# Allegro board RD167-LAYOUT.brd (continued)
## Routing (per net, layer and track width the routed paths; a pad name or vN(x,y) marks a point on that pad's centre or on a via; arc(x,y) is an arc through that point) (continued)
+12V_Q6: length 28.9
  TOP w0.2: TP27.1 216.6,208.9
  TOP w0.5: 220.18,220.5 219.31,220.5 ; 220.45,219.27 220.45,220.23 ; 218.78,220.5 v2(217.75,220.5)
  TOP w0.6: v2(211.44,211.26) v2(213,211.26)
  TOP w0.7: 219.31,220.5 218.78,220.5
  TOP w0.8: C105.1 220.45,219.27 ; 220.45,220.23 R80.1 220.18,220.5
  CONDUCTIVE5 w0.5: v2(211.44,211.26) v2(213,211.26) 215.25,213.51 215.25,218 v2(217.75,220.5)
  BOTTOM w0.6: IC14.13 209.75,212.37 209.91,212.2 210.4,212.2 ; R89.1 211.44,210.46 v2(211.44,211.26) ; R90.1 213.3,210.74 v2(213,211.26) v2(211.44,211.26) ; C108.1 v2(211.44,211.26) ; v2(211.44,211.26) 210.67,210.48 210.5,210.03
  BOTTOM w0.8: C109.1 210.5,210.03 ; 210.4,212.2 C108.1
+12V_Q7: length 28.9
  TOP w0.2: TP32.1 216.6,158.9
  TOP w0.5: 220.45,169.27 220.45,170.23 ; 220.18,170.5 219.31,170.5 ; 218.78,170.5 v2(217.75,170.5)
  TOP w0.6: v2(211.44,161.26) v2(213,161.26)
  TOP w0.7: 219.31,170.5 218.78,170.5
  TOP w0.8: C117.1 220.45,169.27 ; 220.18,170.5 R92.1 220.45,170.23
  CONDUCTIVE5 w0.5: v2(211.44,161.26) v2(213,161.26) 215.25,163.51 215.25,168 v2(217.75,170.5)
  BOTTOM w0.6: v2(211.44,161.26) 210.67,160.48 210.5,160.03 ; v2(211.44,161.26) C120.1 ; v2(211.44,161.26) 211.44,160.46 R101.1 ; v2(211.44,161.26) v2(213,161.26) 213.3,160.74 R102.1 ; IC16.13 209.75,162.37 209.91,162.2 210.4,162.2
  BOTTOM w0.8: 210.4,162.2 C120.1 ; C121.1 210.5,160.03
+12V_Q8: length 28.9
  TOP w0.2: TP37.1 216.6,120.9
  TOP w0.5: 220.45,131.27 220.45,132.23 ; 218.78,132.5 v2(217.75,132.5) ; 220.18,132.5 219.31,132.5
  TOP w0.6: v2(211.44,123.26) v2(213,123.26)
  TOP w0.7: 219.31,132.5 218.78,132.5
  TOP w0.8: 220.45,132.23 R104.1 220.18,132.5 ; C137.1 220.45,131.27
  CONDUCTIVE5 w0.5: v2(211.44,123.26) v2(213,123.26) 215.25,125.51 215.25,130 v2(217.75,132.5)
  BOTTOM w0.6: v2(211.44,123.26) 211.44,122.46 R113.1 ; v2(211.44,123.26) 210.67,122.48 210.5,122.03 ; v2(211.44,123.26) C140.1 ; v2(211.44,123.26) v2(213,123.26) 213.3,122.74 R114.1 ; IC18.13 209.75,124.36 209.91,124.2 210.4,124.2
  BOTTOM w0.8: 210.4,124.2 C140.1 ; C141.1 210.5,122.03
+20V_Q1: length 27.8
  TOP w0.2: TP2.1 103.4,118.1
  TOP w0.5: C19.1 104.25,108 104.75,107.5 v2(104.75,106.5) 103.55,106.5
  TOP w0.6: v2(108.56,115.74) v2(107,115.74)
  TOP w0.8: R21.1 103.55,106.5
  CONDUCTIVE5 w0.5: v2(104.75,106.5) 104.75,113.49 v2(107,115.74) v2(108.56,115.74)
  BOTTOM w0.6: 109.61,114.8 110.08,114.8 110.25,114.64 IC4.13 ; v2(108.56,115.74) 109.33,116.52 109.5,116.97 ; v2(108.56,115.74) C24.1 ; v2(108.56,115.74) 108.56,116.54 R30.1 ; v2(108.56,115.74) v2(107,115.74) 106.7,116.26 R31.1
  BOTTOM w0.8: C23.1 109.5,116.97 ; 109.61,114.8 C24.1
+20V_Q2: length 27.8
  TOP w0.2: TP7.1 103.4,156.1
  TOP w0.5: C39.1 104.25,146 104.75,145.5 v2(104.75,144.5) 103.55,144.5
  TOP w0.6: v2(108.56,153.74) v2(107,153.74)
  TOP w0.8: R32.1 103.55,144.5
  CONDUCTIVE5 w0.5: v2(104.75,144.5) 104.75,151.49 v2(107,153.74) v2(108.56,153.74)
  BOTTOM w0.6: 109.5,154.97 109.33,154.52 v2(108.56,153.74) ; v2(108.56,153.74) v2(107,153.74) 106.7,154.26 R43.1 ; v2(108.56,153.74) C44.1 ; v2(108.56,153.74) 108.56,154.54 R42.1 ; 109.61,152.8 110.08,152.8 110.25,152.63 IC6.13
  BOTTOM w0.8: 109.61,152.8 C44.1 ; C43.1 109.5,154.97
+20V_Q3: length 27.8
  TOP w0.2: TP12.1 103.4,206.1
  TOP w0.5: C51.1 104.25,196 104.75,195.5 v2(104.75,194.5) 103.55,194.5
  TOP w0.6: v2(108.56,203.74) v2(107,203.74)
  TOP w0.8: R45.1 103.55,194.5
  CONDUCTIVE5 w0.5: v2(104.75,194.5) 104.75,201.49 v2(107,203.74) v2(108.56,203.74)
  BOTTOM w0.6: v2(108.56,203.74) 108.56,204.54 R54.1 ; v2(108.56,203.74) v2(107,203.74) 106.7,204.26 R55.1 ; v2(108.56,203.74) C56.1 ; v2(108.56,203.74) 109.33,204.52 109.5,204.97 ; 109.61,202.8 110.08,202.8 110.25,202.63 IC8.13
  BOTTOM w0.8: 109.61,202.8 C56.1 ; C55.1 109.5,204.97
+20V_Q4: length 27.8
  TOP w0.2: TP17.1 103.4,244.1
  TOP w0.5: C71.1 104.25,234 104.75,233.5 v2(104.75,232.5) 103.55,232.5
  TOP w0.6: v2(108.56,241.74) v2(107,241.74)
  TOP w0.8: R57.1 103.55,232.5
  CONDUCTIVE5 w0.5: v2(104.75,232.5) 104.75,239.49 v2(107,241.74) v2(108.56,241.74)
  BOTTOM w0.6: IC10.13 110.25,240.63 110.08,240.8 109.61,240.8 ; v2(108.56,241.74) 109.33,242.52 109.5,242.97 ; v2(108.56,241.74) C76.1 ; v2(108.56,241.74) v2(107,241.74) 106.7,242.26 R67.1 ; v2(108.56,241.74) 108.56,242.54 R66.1
  BOTTOM w0.8: C75.1 109.5,242.97 ; 109.61,240.8 C76.1
+24V: length 59.9
  TOP w0.3: 145.27,262 147.25,262 148,262.75 v2(148,264.25)
  TOP w0.8: 167,267.35 v2(167,265.75) v2(167,264.25) ; 148,267.35 v2(148,265.75) v2(148,264.25) ; v2(171,264.25) v2(171,265.75) 171,267.35
  TOP w1: CN2.1 148,267.35 ; CN3.1 167,267.35 ; CN3.3 171,267.35
  TOP w1.7: TP43.1 145.27,262
  CONDUCTIVE2 w0.5: PS8.1 196.63,173.55 ; PS8.1 196.63,170.45 ; PS8.1 195.08,172 ; PS2.1 123.37,106.55 ; PS2.1 123.37,103.45 ; PS2.1 124.92,105 ; PS3.1 123.37,141.45 ; PS3.1 124.92,143 ; PS3.1 123.37,144.55 ; PS7.1 195.08,222 ; PS7.1 196.63,223.55 ; PS7.1 196.63,220.45 ; PS4.1 124.92,193 ; PS4.1 123.37,191.45 ; PS4.1 123.37,194.55 ; PS5.1 124.92,231 ; PS5.1 123.37,229.45 ; PS5.1 123.37,232.55 ; PS6.1 195.08,260 ; PS6.1 196.63,261.55 ; PS6.1 196.63,258.45 ; PS9.1 195.08,134 ; PS9.1 196.63,135.55 ; PS9.1 196.63,132.45
  BOTTOM w0.8: v2(148,264.25) v2(148,265.75) ; v2(171,264.25) v2(171,265.75) ; v2(167,264.25) v2(167,265.75)
  vias: v2(163.75,254) v2(163.75,252.5)
GND: length 1762.2
  TOP w0.2: 162.98,155.25 164.75,155.25 v1(165,155) ; 157.18,167.44 156.31,167.44 v1(156,167.75) ; v1(165,157) 164.25,156.25 162.98,156.25 ; v1(165,157) 164.25,157.75 163.75,157.75 163.25,157.25 162.91,157.25 ; v1(165,157) 165,157.75 164.5,158.25 162.98,158.25 ; 162.98,153.75 163.75,153.75 v1(164,154) 163.75,154.25 162.98,154.25 ; v1(155,155) 155.25,155.25 157.02,155.25 ; 157.02,164.75 156.25,164.75 v1(156,164.5) ; 162.98,162.25 163.5,162.25 v1(164,162.75) ; 157.02,162.25 156.25,162.25 v1(156,162.5) ; 157.02,157.25 156.5,157.25 v1(156,157.75) 156.5,158.25 157.02,158.25 ; v1(164,160.5) 163.75,160.25 162.98,160.25 ; v1(155,157) 155.75,156.25 157.02,156.25 ; v1(164,168) 163.44,167.44 162.7,167.44 ; 157.02,154.25 156.25,154.25 v1(156,154) 156.25,153.75 157.02,153.75 ; v1(156,160.5) 156.25,160.25 157.02,160.25
  TOP w0.25: CN4.11 162.98,155.25 ; CN4.16 157.02,156.25 ; CN4.23 162.98,158.25 ; CN4.50 157.02,164.75 ; CN4.24 157.02,158.25 ; CN4.32 157.02,160.25 ; CN4.6 157.02,153.75 ; CN4.31 162.98,160.25 ; CN4.12 157.02,155.25 ; CN4.15 162.98,156.25 ; CN4.39 162.98,162.25 ; CN4.7 162.98,154.25 ; CN4.40 157.02,162.25 ; CN4.20 157.02,157.25 ; CN4.19 162.91,157.25 ; CN4.8 157.02,154.25 ; CN4.5 162.98,153.75
  TOP w0.3: v1(178.75,39) 180,40.25 180,41.51 ; v1(141.25,71.25) 140,70 140,68.74 ; 146.16,52 v1(144.75,52) ; v1(145.5,60.75) 146.5,60.75 146.84,61.09 146.84,61.8 ; TP45.1 v1(148,20) ; v1(137,243.75) 138,243.75 138.75,243 138.75,212.25 136.25,209.75 136.25,206.5 v1(137,205.75) 138,205.75 138.75,205 138.75,160.25 136.25,157.75 136.25,156.5 v1(137,155.75) 137.75,155.75 138.75,154.75 138.75,122.25 136.25,119.75 136.25,118.5 v1(137,117.75) 138,117.75 140.25,120 140.25,205.75 v1(138,208) ; 161.25,80.2 161.25,80.65 162.05,81.45 162.05,82.06 ; 170,215 170,189.25 168.25,187.5 163.75,187.5 v1(162.25,186) ; v1(183,121.25) 182,121.25 181.25,122 181.25,153.5 183.75,156 183.75,158.5 v1(183,159.25) 182,159.25 181.25,160 181.25,204.75 183.75,207.25 183.75,208.5 v1(183,209.25) 182.25,209.25 181.25,210.25 181.25,242.75 183.75,245.25 183.75,246.5 v1(183,247.25) 181.5,247.25 ; 150,26.01 v1(150,24.5) ; v1(176.25,25.75) 176.7,26.2 177.83,26.2 ; 162.24,82.25 v1(163.5,82.25) ; 146.86,53.75 v1(144.75,53.75) ; IC1.11 v1(158,73.75) 159.5,75.25 160.26,75.25 ; IC24.11 v1(173,73.75) ; v1(182,157) 179.75,159.25 179.75,244 ; 178.19,26.2 179.25,26.2 179.5,25.95 180.88,25.95 ; 152.54,60.8 153.55,60.8 v1(154,61.25)
  TOP w0.4: 159,12.5 v1(159,14)
  TOP w0.45: C8.2 146.86,53.75
  TOP w0.5: 142.17,37.8 143.3,37.8 v1(143.75,38.25) ; 139.12,38.05 140.75,38.05 141,37.8 141.72,37.8 ; IC23.2 161.25,80.2
  TOP w0.6: CN4.59 162.7,167.44 ; CN4.60 157.18,167.44 ; IC19.4 146.84,61.8
  TOP w0.8: 160.43,237.6 161.91,237.6 v2(162.5,237.5) ; 141.72,37.8 C1.2 142.17,37.8 ; 180,41.51 C153.2 ; 162.24,82.25 C174.2 162.05,82.06 ; D3.A 146.16,52 ; 177.83,26.2 C146.2 178.19,26.2 ; 159.57,237.6 157.65,237.6 157.6,237.65 PS11.7 ; 160.26,75.25 C175.2 ; C10.2 140,68.74 ; LED1.K 150,26.01 ; C158.2 152.54,60.8
  TOP w1: CN1.2 159,12.5
  TOP w1.2: 159.57,237.6 C163.2 160.43,237.6
  TOP w1.5: 139.12,38.05 CT1.13 ; 180.88,25.95 CT2.13
  CONDUCTIVE3 w0.5: PS11.7 156.45,237.65 ; PS11.7 155,239.1 ; PS11.7 153.55,237.65 ; PS11.7 155,236.2 ; CT1.13 140.42,38.05 ; CT2.13 179.58,25.95
  CONDUCTIVE4 w0.5: CT2.13 179.58,25.95 ; CT1.13 140.42,38.05 ; 153.55,237.65 PS11.7 156.45,237.65 ; 139.08,54.75 PS1.2 139.08,51.75 ; 181.42,54.75 PS10.2 181.42,57.75
  CONDUCTIVE5 w0.2: v1(124.1,114.64) 124.1,115.5 ; v1(124.1,202.63) 124.1,203.5 ; v1(124.1,152.63) 124.1,153.5 ; v1(124.1,240.63) 124.1,241.6
  CONDUCTIVE5 w0.3: 179.75,27.35 179.75,27.33 CT2.13 179.75,24.57 179.75,24.55 ; 140.25,36.7 140.22,36.7 CT1.13 140.22,39.4 140.25,39.4
  CONDUCTIVE5 w0.5: 139.08,54.75 PS1.2 139.08,51.75 ; 181.42,57.75 PS10.2 181.42,54.7
  BOTTOM w0.2: 163.12,138.93 163.12,140.5 ; 163.12,140.5 162.47,140.5 ; 163.12,140.5 163.78,140.5 ; 163.78,140.5 v1(165.25,140.5) ; 163.78,140.5 163.78,138.93 ; 162.47,140.5 162,140.5 161.82,140.32 161.82,138.93 ; 162.47,140.5 162.47,138.93
  BOTTOM w0.25: 196.93,168.88 194.55,168.88 ; v1(165.75,178.25) 176.75,167.25 176.75,126.5 182,121.25 v1(183,121.25) ; 123.08,146.12 125.45,146.12 ; 196.93,130.88 194.55,130.88 ; v1(183,159.25) 182,159.25 178.25,163 178.25,167.75 v1(167.25,178.75) ; v1(162.5,130) 147.25,130 140.75,136.5 140.75,202.75 137.75,205.75 v1(137,205.75) ; v1(138,208) 140.75,210.75 140.75,238.5 138.25,241 128.7,241 v1(127.7,240) ; v1(192.3,251) 191.3,250 183.25,250 v1(181.5,248.25) 176.75,243.5 176.75,192.25 v1(165.75,181.25) ; v1(167.25,180.75) 178.25,191.75 178.25,212 ; v1(137,243.75) 137.75,243.75 142.25,239.25 142.25,139.25 149.75,131.75 157.5,131.75 158,131.25 v1(163.75,131.25) ; 146.25,127 146.75,127.5 v1(162.5,127.5) ; 146.25,127 137.75,135.5 137.75,152.25 137,153 128.7,153 v1(127.7,152) ; 146.25,127 v1(137,117.75) ; v1(163.75,126.25) 163.25,125.75 147.5,125.75 v1(138.5,116.75) 136.75,115 128.7,115 v1(127.7,114) ; v1(183,209.25) 179.75,206 179.75,191.25 v1(168.25,179.75) 179.75,168.25 179.75,164 181.75,162 191.3,162 v1(192.3,163) ; v1(192.3,125) 191.3,124 182.25,124 178.25,128 178.25,153.25 v1(182,157) ; 196.93,256.88 194.55,256.88 ; 196.93,218.88 194.55,218.88 ; v1(192.3,213) 191.3,212 178.25,212 ; 123.08,234.12 125.45,234.12 ; 178.25,212 178.25,242.5 v1(183,247.25) ; 123.08,108.12 125.45,108.12 ; 123.08,196.12 125.45,196.12 ; v1(163.75,128.75) 146.5,128.75 139.25,136 139.25,154.25 137.75,155.75 v1(137,155.75) 139.25,158 139.25,201.75 138,203 128.7,203 v1(127.7,202)
  BOTTOM w0.3: C166.2 163.25,189.75 162.75,190.25 v1(161.25,190.25) 161.25,188.99 ; 164.51,139 164.51,139.76 v1(165.25,140.5) ; C164.2 155.7,136.3 v1(155.25,136.75) 155.25,139 156,139.75 158,139.75 158.49,139.26 158.49,138.84 ; v1(124.1,240.63) 124.77,241.3 126.6,241.3 127.7,242.4 135.65,242.4 v1(137,243.75) ; 163.78,184.75 163.25,184.75 163.12,184.62 IC22.8 ; 163.78,184.75 IC22.9 ; 163.78,184.75 164.25,184.75 164.51,184.49 164.51,184 ; v1(183,209.25) 184.35,210.6 192.3,210.6 193.4,211.7 195.24,211.7 v1(195.9,212.37) ; 142.95,63.7 142.95,62.7 v1(142.5,62.25) ; v1(183,121.25) 184.35,122.6 192.3,122.6 193.4,123.7 195.24,123.7 v1(195.9,124.36) ; v1(164.75,181.5) 164.51,181.74 164.51,182.8 ; 177.05,45.19 177.05,46.31 ; v1(124.1,114.64) 124.77,115.3 126.6,115.3 127.7,116.4 135.65,116.4 v1(137,117.75) ; 169.74,73.75 v1(173,73.75) ; v1(195.9,162.37) 195.24,161.7 193.4,161.7 192.3,160.6 184.35,160.6 v1(183,159.25) ; 156.69,136.3 158.2,136.3 159.22,135.28 IC21.19 ; v1(177.5,48) 177.05,47.55 177.05,46.55 ; 154.74,73.75 v1(158,73.75) ; v1(178.75,39) 179.06,38.69 IC20.5 ; v1(137,155.75) 135.65,154.4 127.7,154.4 126.6,153.3 124.77,153.3 v1(124.1,152.63) ; C165.2 155.7,181.3 v1(155.25,181.75) 155.75,182.25 158.25,182.25 158.49,182.49 158.49,182.96 ; IC22.19 159.22,180.32 158.25,181.3 156.69,181.3 ; v1(137,205.75) 135.65,204.4 127.7,204.4 126.6,203.3 124.77,203.3 v1(124.1,202.63) ; v1(195.9,250.37) 195.24,249.7 193.4,249.7 192.3,248.6 184.35,248.6 v1(183,247.25) ; 142.95,65.06 142.95,63.94 ; v1(141.25,71.25) 140.94,71.56 IC2.5 ; 167.75,129.25 167.75,135.75
  BOTTOM w0.35: IC21.6 161.82,138.93 ; IC21.7 162.47,138.93 ; IC21.9 163.78,138.93 ; IC21.8 163.12,138.93
  BOTTOM w0.5: v1(124.1,240.63) 122.48,240.63 ; v1(195.9,212.37) 197.52,212.37 ; 195.6,246.2 194.5,246.2 ; 196.03,208.2 196.7,208.2 197.06,208.56 197.52,208.56 ; v1(195.9,124.36) 197.52,124.36 ; C160.2 181.42,54.37 PS10.2 ; 164.51,184 IC22.10 164.51,182.8 ; IC21.10 164.51,139 ; 122.48,118.44 122.94,118.44 123.3,118.8 123.97,118.8 ; 195.6,120.2 194.5,120.2 ; 122.48,156.44 122.94,156.44 123.3,156.8 123.97,156.8 ; 139.7,56.55 139.7,57.55 v1(139.25,58) ; v1(124.1,202.63) 122.48,202.63 ; 124.39,118.8 125.5,118.8 ; v1(195.9,250.37) 197.52,250.37 ; IC22.1 158.49,182.96 ; 124.39,244.8 125.5,244.8 ; v1(195.9,162.37) 197.52,162.37 ; 122.48,244.44 122.94,244.44 123.3,244.8 123.97,244.8 ; PS1.2 139.7,53.87 139.7,56.23 ; 123.97,206.8 123.3,206.8 122.94,206.44 122.48,206.44 ; 180.8,53.58 180.8,52.45 v1(181.25,52) ; 196.03,246.2 196.7,246.2 197.06,246.56 197.52,246.56 ; v1(124.1,114.64) 122.48,114.64 ; 195.6,208.2 194.5,208.2 ; 195.6,158.2 194.5,158.2 ; 197.52,158.56 197.06,158.56 196.7,158.2 196.03,158.2 ; 124.39,156.8 125.5,156.8 ; IC21.1 158.49,138.84 ; 124.39,206.8 125.5,206.8 ; 197.52,120.56 197.06,120.56 196.7,120.2 196.03,120.2 ; v1(124.1,152.63) 122.48,152.63
  BOTTOM w0.6: 122.48,240.63 IC10.4 ; 122.48,114.64 IC4.4 ; 122.48,244.44 IC10.1 ; 122.48,206.44 IC8.1 ; 122.48,202.63 IC8.4 ; 122.48,118.44 IC4.1 ; 197.52,250.37 IC12.4 ; 122.48,152.63 IC6.4 ; 197.52,124.36 IC18.4 ; 197.52,246.56 IC12.1 ; 197.52,158.56 IC16.1 ; 197.52,162.37 IC16.4 ; 197.52,120.56 IC18.1 ; 197.52,208.56 IC14.1 ; 197.52,212.37 IC14.4 ; 122.48,156.44 IC6.1
  BOTTOM w0.8: C167.2 161.25,188.99 ; R129.1 177.05,45.19 ; C172.2 169.74,73.75 ; 177.05,46.55 C159.1 177.05,46.31 ; 195.6,158.2 C119.2 196.03,158.2 ; 124.39,118.8 C25.2 123.97,118.8 ; C164.2 156.69,136.3 ; 196.03,120.2 C139.2 195.6,120.2 ; 123.97,244.8 C77.2 124.39,244.8 ; C160.2 180.8,53.58 ; 142.95,63.94 C12.1 142.95,63.7 ; 123.97,156.8 C45.2 124.39,156.8 ; 139.7,56.23 C17.2 139.7,56.55 ; 195.6,208.2 C107.2 196.03,208.2 ; C165.2 156.69,181.3 ; 196.03,246.2 C87.2 195.6,246.2 ; R8.1 142.95,65.06 ; 124.39,206.8 C57.2 123.97,206.8 ; C13.2 154.74,73.75
  vias: v1(126.5,243.5) v1(126.5,205.5) v1(126.5,155.5) v1(126.5,117.5) v1(137,235) v1(137,230) v1(137,225) v1(137,220) v1(137,215) v1(137,200) v1(137,195) v1(137,190) v1(137,185) v1(137,180) v1(137,175) v1(137,170) v1(137,165) v1(137,150) v1(137,145) v1(137,140) v1(137,135) v1(137,130) v1(137,125) v1(137.5,251) v1(140,110) v1(140,105) v1(140,100) v1(140,80) v1(140,75) v1(140,30) v1(140,25) v1(140,20) v1(140,15) v1(142,45) v1(144,5) v1(145,240) v1(145,235) v1(145,230) v1(145,225) v1(145,220) v1(145,215) v1(145,210) v1(145,205) v1(145,200) v1(145,195) v1(145,190) v1(145,185) v1(145,180) v1(145,175) v1(145,170) v1(145,165) v1(145,160) v1(145,155) v1(145,150) v1(145,145) v1(145,140) v1(145,135) v1(145,120) v1(145,115) v1(145,110) v1(145,105) v1(145,100) v1(145,95) v1(145,90) v1(145,85) v1(145,80) v1(145,30) v1(145,25) v1(145,20) v1(145,15) v1(145,10) v1(150,230) v1(150,225) v1(150,220) v1(150,215) v1(150,210) v1(150,205) v1(150,200) v1(150,195) v1(150,190) v1(150,185) v1(150,180) v1(150,175) v1(150,170) v1(150,165) v1(150,160) v1(150,155) v1(150,150) v1(150,145) v1(150,140) v1(150,135) v1(150,120) v1(150,115) v1(150,110) v1(150,105) v1(150,100) v1(150,95) v1(150,90) v1(150,85) v1(150,15) v1(150,10) v1(150,5) v1(154,43) v1(154,35) v1(155,230) v1(155,225) v1(155,220) v1(155,200) v1(155,195) v1(155,120) v1(155,115) v1(155,105) v1(155,100) v1(155,84) v1(155,65) v1(155,50) v1(155,15) v1(155,10) v1(160,230) v1(160,225) v1(160,220) v1(160,200) v1(160,195) v1(160,120) v1(160,110) v1(160,105) v1(160,100) v1(160,65) v1(160,60) v1(160,55) v1(160,50) v1(160,45) v1(160,40) v1(160,35) v1(160,30) v1(160,25) v1(165,240) v1(165,235) v1(165,230) v1(165,225) v1(165,220) v1(165,115) v1(165,65) v1(165,60) v1(165,55) v1(165,50) v1(165,45) v1(165,40) v1(165,25) v1(165,20) v1(165,15) v1(165,10) v1(166,185) v1(169,122) v1(169,110) v1(169,100) v1(169,95) v1(169,84) v1(170,240) v1(170,235) v1(170,230) v1(170,225) v1(170,220) v1(170,180) v1(170,170) v1(170,165) v1(170,160) v1(170,65) v1(170,60) v1(170,55) v1(170,50) v1(170,45) v1(170,40) v1(170,35) v1(170,20) v1(170,15) v1(170,10) v1(170,5) v1(172,84) v1(175,240) v1(175,235) v1(175,230) v1(175,225) v1(175,220) v1(175,215) v1(175,210) v1(175,205) v1(175,200) v1(175,195) v1(175,185) v1(175,180) v1(175,175) v1(175,165) v1(175,160) v1(175,155) v1(175,150) v1(175,145) v1(175,140) v1(175,135) v1(175,130) v1(175,125) v1(175,120) v1(175,115) v1(175,110) v1(175,105) v1(175,100) v1(175,95) v1(175,90) v1(175,85) v1(175,35) v1(175,30) v1(175,15) v1(175,10) v1(176,5) v1(178,249) v1(179,188) v1(179,180) v1(179,175) v1(180,120) v1(180,110) v1(180,105) v1(180,100) v1(180,80) v1(180,75) v1(180,70) v1(180,65) v1(180,60) v1(180,35) v1(180,15) v1(183,240) v1(183,235) v1(183,230) v1(183,225) v1(183,220) v1(183,215) v1(183,205) v1(183,200) v1(183,195) v1(183,190) v1(183,185) v1(183,180) v1(183,175) v1(183,170) v1(183,165) v1(183,150) v1(183,145) v1(183,140) v1(183,135) v1(183,130) v1(193.5,247.5) v1(193.5,209.5) v1(193.5,159.5) v1(193.5,121.5)
GND_24V: length 109.4
  TOP w0.3: 174.73,262 173.25,262 173,262.25 v2(173,264.25)
  TOP w0.8: 173,267.35 v2(173,265.75) v2(173,264.25) ; v2(152,264.25) v2(152,265.75) 152,267.35 ; v2(169,264.25) v2(169,265.75) 169,267.35
  TOP w1: CN3.4 173,267.35 ; CN2.3 152,267.35 ; CN3.2 169,267.35
  TOP w1.7: TP46.1 174.73,262
  CONDUCTIVE3 w0.5: 120.83,106.55 PS2.2 120.83,103.45 ; 120.83,194.55 PS4.2 120.83,191.45 ; 199.17,220.45 PS7.2 199.17,223.55 ; 120.83,229.45 PS5.2 120.83,232.55 ; 120.83,144.55 PS3.2 120.83,141.45 ; PS11.1 156.45,252.89 ; PS11.1 153.55,252.89 ; PS11.1 155,254.34 ; 199.17,135.55 PS9.2 199.17,132.45 ; 199.17,261.55 PS6.2 199.17,258.45 ; 199.17,173.55 PS8.2 199.17,170.45
  CONDUCTIVE4 w0.5: 120.83,141.45 PS3.2 120.83,144.55 ; 120.83,103.45 PS2.2 120.83,106.55 ; PS11.1 155,254.34 ; PS11.1 156.45,252.89 ; PS11.1 153.55,252.89 ; 199.17,223.55 PS7.2 199.17,220.45 ; 199.17,261.55 PS6.2 199.17,258.45 ; 120.83,229.45 PS5.2 120.83,232.55 ; 199.17,135.55 PS9.2 199.17,132.45 ; 120.83,191.45 PS4.2 120.83,194.55 ; 199.17,173.55 PS8.2 199.17,170.45
  CONDUCTIVE5 w0.5: 199.17,223.55 PS7.2 199.17,220.45 ; 120.83,106.55 PS2.2 120.83,103.45 ; 199.17,135.55 PS9.2 199.17,132.45 ; 120.83,194.55 PS4.2 120.83,191.45 ; 199.17,173.55 PS8.2 199.17,170.45 ; PS11.1 155,254.34 ; PS11.1 156.45,252.89 ; PS11.1 153.55,252.89 ; 199.17,261.55 PS6.2 199.17,258.45 ; 120.83,144.55 PS3.2 120.83,141.45 ; 120.83,229.45 PS5.2 120.83,232.55
  BOTTOM w0.8: v2(169,264.25) v2(169,265.75) ; v2(152,264.25) v2(152,265.75) ; v2(173,264.25) v2(173,265.75)
  vias: v2(121.25,261.25) v2(121.25,251.25) v2(126.25,256.25) v2(131.25,261.25) v2(136.25,266.25) v2(136.5,256.25) v2(138.75,276.25) v2(140,261.25) v2(141.25,271.25) v2(142.5,256.25) v2(143.75,266.25) v2(147.5,256.25) v2(147.5,250) v2(151.25,261.25) v2(156.25,276.5) v2(156.25,267.5) v2(156.25,261.25) v2(162.5,276.25) v2(162.5,267.5) v2(162.5,261.25) v2(163.75,258.5) v2(163.75,257) v2(168.75,261.25) v2(168.75,255) v2(168.75,248.75) v2(175,255) v2(178.75,272.5) v2(181.25,276.25) v2(181.25,268.75) v2(181.25,262.5) v2(181.25,256.25)
GND_DC_PRI: length 32.8
  TOP w0.3: 130,68.74 130,70.55 v1(128.75,71.8)
  TOP w0.8: C11.2 130,68.74
  CONDUCTIVE2 w0.8: v1(128.75,71.8) 131.25,69.3 v1(131.25,60)
  BOTTOM w0.3: 127.19,71.8 v1(128.75,71.8)
  BOTTOM w0.5: 128.59,58.5 129.75,58.5 ; 130.65,73.25 IC2.4 128.99,71.56 v1(128.75,71.8) ; C16.2 128.3,57.3 128.4,57.4 128.4,57.98 ; 128.4,58.9 128.4,60 ; 127,72.05 127,73.25 ; PS1.5 131.46,55 ; 128.3,56.35 128.3,55.25 ; 128.54,56.5 129.75,56.5
  BOTTOM w0.8: 128.4,57.98 R19.2 ; R19.2 128.59,58.5 ; R19.2 128.4,58.9 ; 127.19,71.8 R17.2 127,72.05 ; 128.3,56.35 C16.2 128.54,56.5
GND_DC_SEC: length 34.4
  TOP w0.3: C155.2 191.5,40.2 v1(191.5,38.45)
  CONDUCTIVE2 w0.8: v1(188.75,51) 188.75,41.2 v1(191.5,38.45)
  BOTTOM w0.5: 190.25,54.75 191.5,54.75 191.7,54.55 191.7,54.02 ; IC20.4 189.35,37 ; 192.73,38.45 v1(191.5,38.45) 191.26,38.69 189.41,38.69 ; 191.41,52 190.25,52 ; 191.7,53.48 191.7,52.95 191.6,52.85 191.6,52.25 ; 191.46,53.75 190.25,53.75 ; PS10.5 189.04,54.5 ; 193,38.2 193,37 ; 191.6,51.73 191.6,50.75
  BOTTOM w0.8: C161.2 191.46,53.75 ; C161.2 191.7,54.02 ; C161.2 191.7,53.48 ; 192.73,38.45 R130.2 193,38.2 ; R132.2 191.41,52 ; R132.2 191.6,51.73 ; R132.2 191.6,52.25
  BOTTOM w1.5: IC20.4 189.41,38.69
GND_Q1: length 23.6
  TOP w0.3: 97.36,116.25 97.36,116.86 98,117.5 98,119.23
  TOP w0.5: v2(96.25,106.5) 98,106.5 98.47,106.45
  TOP w0.6: IC3.3 97.36,116.25 ; 96.09,113.25 IC3.4 96.09,117.59 TP6.1
  TOP w0.8: R22.2 98.47,106.45
  TOP w1.7: 98,119.23 TP6.1
  BOTTOM w0.6: 107.22,114 107.7,114 v2(108.25,113.75) ; IC4.12 110.25,113.36 110.08,113.2 109.61,113.2 ; 107.09,111.95 v2(108.25,111.95) ; v2(108.25,111.95) 108.25,110.64 108.1,110.06 ; v2(108.25,111.95) 108.83,112.08 109.5,112.75 C24.2
  BOTTOM w0.8: 106.9,111.95 107.09,111.95 ; 109.61,113.2 C24.2 ; C31.2 107.22,114
  BOTTOM w1: D12.A 108.1,110.06
  vias: v2(112.25,108) v2(114,108)
GND_Q2: length 23.6
  TOP w0.3: 97.36,154.25 97.36,154.87 98,155.5 98,157.23
  TOP w0.5: 98.47,144.45 98,144.5 v2(96.25,144.5)
  TOP w0.6: IC5.3 97.36,154.25 ; TP11.1 96.09,155.59 IC5.4 96.09,151.25
  TOP w0.8: R33.2 98.47,144.45
  TOP w1.7: 98,157.23 TP11.1
  BOTTOM w0.6: C44.2 109.5,150.75 108.83,150.08 v2(108.25,149.95) ; 107.09,149.95 v2(108.25,149.95) ; v2(108.25,149.95) 108.25,148.64 108.1,148.06 ; IC6.12 110.25,151.37 110.08,151.2 109.61,151.2 ; 107.22,152 107.7,152 v2(108.25,151.75)
  BOTTOM w0.8: 109.61,151.2 C44.2 ; C49.2 107.22,152 ; 106.9,149.95 107.09,149.95
  BOTTOM w1: D18.A 108.1,148.06
  vias: v2(112.25,146) v2(114,146)
GND_Q3: length 23.6
  TOP w0.3: 98,207.23 98,205.5 97.36,204.87 97.36,204.25
  TOP w0.5: 98.47,194.45 98,194.5 v2(96.25,194.5)
  TOP w0.6: TP16.1 96.09,205.59 IC7.4 96.09,201.25 ; IC7.3 97.36,204.25
  TOP w0.8: R46.2 98.47,194.45
  TOP w1.7: 98,207.23 TP16.1
  BOTTOM w0.6: 108.1,198.06 108.25,198.64 v2(108.25,199.95) ; IC8.12 110.25,201.37 110.08,201.2 109.61,201.2 ; 107.22,202 107.7,202 v2(108.25,201.75) ; v2(108.25,199.95) 108.83,200.08 109.5,200.75 C56.2 ; v2(108.25,199.95) 107.09,199.95
  BOTTOM w0.8: 106.9,199.95 107.09,199.95 ; 109.61,201.2 C56.2 ; C61.2 107.22,202
  BOTTOM w1: D24.A 108.1,198.06
  vias: v2(112.25,196) v2(114,196)
GND_Q4: length 23.6
  TOP w0.3: 97.36,242.25 97.36,242.87 98,243.5 98,245.23
  TOP w0.5: v2(96.25,232.5) 98,232.5 98.47,232.45
  TOP w0.6: IC9.3 97.36,242.25 ; 96.09,239.25 IC9.4 96.09,243.59 TP21.1
  TOP w0.8: R58.2 98.47,232.45
  TOP w1.7: 98,245.23 TP21.1
  BOTTOM w0.6: 107.22,240 107.7,240 v2(108.25,239.75) ; 107.09,237.95 v2(108.25,237.95) ; v2(108.25,237.95) 108.25,236.64 108.1,236.06 ; v2(108.25,237.95) 108.83,238.08 109.5,238.75 C76.2 ; 109.61,239.2 110.08,239.2 110.25,239.37 IC10.12
  BOTTOM w0.8: 109.61,239.2 C76.2 ; C81.2 107.22,240 ; 106.9,237.95 107.09,237.95
  BOTTOM w1: D30.A 108.1,236.06
  vias: v2(112.25,234) v2(114,234)
GND_Q5: length 23.5
  TOP w0.3: 222.63,248.75 222.63,248.13 222,247.5 222,245.77
  TOP w0.5: R70.2 226.45,257.6 226.05,258 225.5,258 v2(225,258.5)
  TOP w0.6: IC11.3 222.63,248.75 ; 223.91,251.75 IC11.4 223.91,247.41 TP26.1
  TOP w1.7: 222,245.77 TP26.1
  BOTTOM w0.6: 210.4,251.8 209.91,251.8 209.75,251.63 IC12.12 ; v2(211.75,253.05) 211.17,252.92 210.5,252.25 C88.2 ; v2(211.75,253.05) 212.91,253.05 ; v2(211.75,253.05) 211.75,254.36 211.9,254.94 ; 212.78,251 212.3,251 v2(211.75,251.25)
  BOTTOM w0.8: 213.1,253.05 212.91,253.05 ; 210.4,251.8 C88.2 ; C92.2 212.78,251
  BOTTOM w1: D36.A 211.9,254.94
  vias: v2(206,257) v2(207.75,257)
GND_Q6: length 23.8
  TOP w0.3: 222,207.77 222,209.5 222.63,210.13 222.63,210.75
  TOP w0.5: 226.45,219.04 226.45,220.05 226,220.5 v2(225,220.5)
  TOP w0.6: IC13.3 222.63,210.75 ; 223.91,213.75 IC13.4 223.91,209.41 TP31.1
  TOP w0.8: R82.2 226.45,219.04
  TOP w1.7: 222,207.77 TP31.1
  BOTTOM w0.6: IC14.12 209.75,213.63 209.91,213.8 210.4,213.8 ; v2(211.75,215.05) 211.17,214.92 210.5,214.25 C108.2 ; v2(211.75,215.05) 211.75,216.36 211.9,216.94 ; v2(211.75,215.05) 212.91,215.05 ; 212.78,213 212.3,213 v2(211.75,213.25)
  BOTTOM w0.8: 210.4,213.8 C108.2 ; C112.2 212.78,213 ; 213.1,215.05 212.91,215.05
  BOTTOM w1: D42.A 211.9,216.94
  vias: v2(206,219) v2(207.75,219)
GND_Q7: length 23.5
  TOP w0.3: 222.63,160.75 222.63,160.13 222,159.5 222,157.77
  TOP w0.5: v2(225,170.5) 225.5,170 226,170 226.45,169.55 R94.2
  TOP w0.6: IC15.3 222.63,160.75 ; TP36.1 223.91,159.41 IC15.4 223.91,163.75
  TOP w1.7: 222,157.77 TP36.1
  BOTTOM w0.6: C120.2 210.5,164.25 211.17,164.92 v2(211.75,165.05) ; 212.91,165.05 v2(211.75,165.05) ; v2(211.75,165.05) 211.75,166.36 211.9,166.94 ; 210.4,163.8 209.91,163.8 209.75,163.63 IC16.12 ; v2(211.75,163.25) 212.3,163 212.78,163
  BOTTOM w0.8: 213.1,165.05 212.91,165.05 ; C124.2 212.78,163 ; 210.4,163.8 C120.2
  BOTTOM w1: D48.A 211.9,166.94
  vias: v2(206,169) v2(207.75,169)
GND_Q8: length 23.8
  TOP w0.3: 222,119.77 222,121.5 222.63,122.14 222.63,122.75
  TOP w0.5: v2(225,132.5) 226,132.5 226.45,132.05 226.45,131.04
  TOP w0.6: IC17.3 222.63,122.75 ; TP41.1 223.91,121.41 IC17.4 223.91,125.75
  TOP w0.8: R106.2 226.45,131.04
  TOP w1.7: 222,119.77 TP41.1
  BOTTOM w0.6: v2(211.75,125.25) 212.3,125 212.78,125 ; 212.91,127.05 v2(211.75,127.05) ; v2(211.75,127.05) 211.75,128.36 211.9,128.94 ; v2(211.75,127.05) 211.17,126.92 210.5,126.25 C140.2 ; 210.4,125.8 209.91,125.8 209.75,125.64 IC18.12
  BOTTOM w0.8: C144.2 212.78,125 ; 213.1,127.05 212.91,127.05 ; 210.4,125.8 C140.2
  BOTTOM w1: D54.A 211.9,128.94
  vias: v2(206,131) v2(207.75,131)
/DI0_BI: length 15.4
  TOP w0.2: 162.98,165.25 163.5,165.25 165,166.75 165,170.75 164,171.75 v1(159,171.75)
  TOP w0.25: CN4.51 162.98,165.25
  BOTTOM w0.2: 159,173.05 v1(159,171.75)
  BOTTOM w0.8: R144.2 159,173.05
/DI1_BI: length 14.9
  TOP w0.2: 157.02,165.25 156,165.25 155.25,166 155.25,170 156,170.75 v1(159,170.75)
  TOP w0.25: CN4.52 157.02,165.25
  BOTTOM w0.2: 161,173.05 161,171.75 160,170.75 v1(159,170.75)
  BOTTOM w0.8: R145.2 161,173.05
/FLT_OUT_HV: length 283.5
  TOP w0.3: v1(137,118.75) 137,119.5 139.5,122 139.5,155 137.75,156.75 v1(137,156.75) 137,157.5 139.5,160 139.5,205.25 138,206.75 v1(137,206.75) 137,209.25 139.5,211.75 139.5,243.25 138,244.75 v1(137,244.75) 137,246.25 137.5,246.75 137.5,248.23 ; v1(161.25,186) 142.5,204.75 142.5,246 140,248.5 137.77,248.5
  TOP w1.7: 137.77,248.5 TP55.1 137.5,248.23
  BOTTOM w0.3: 122.4,241.91 126.31,241.91 127.4,243 135.25,243 v1(137,244.75) ; 161.25,187.08 v1(161.25,186) 161.82,185.43 IC22.6 ; v1(137,156.75) 135.25,155 127.4,155 126.31,153.91 122.4,153.91 ; v1(137,118.75) 135.25,117 127.4,117 126.31,115.91 122.4,115.91 ; 161.06,187.2 159.94,187.2 ; v1(137,206.75) 135.25,205 127.4,205 126.31,203.91 122.4,203.91
  BOTTOM w0.6: IC6.3 122.4,153.91 ; IC10.3 122.4,241.91 ; IC8.3 122.4,203.91 ; IC4.3 122.4,115.91
  BOTTOM w0.8: 161.06,187.2 C167.1 161.25,187.08 ; 159.94,187.2 R142.2
/FLT_OUT_LV: length 284.1
  TOP w0.3: 182.5,116.77 182.5,118.25 183,118.75 v1(183,120.25) 182,120.25 180.5,121.75 180.5,154 183,156.5 v1(183,158.25) 182,158.25 180.5,159.75 180.5,205 183,207.5 v1(183,208.25) 182.25,208.25 180.5,210 180.5,243 183,245.5 v1(183,246.25) 177.5,246.25 172,240.75 172,190.25 168.75,187 164.25,187 v1(163.25,186)
  TOP w1.7: 182.5,116.77 TP56.1
  BOTTOM w0.3: 163.44,187.2 164.56,187.2 ; IC22.7 162.47,185.22 v1(163.25,186) 163.25,187.08 ; v1(183,208.25) 184.75,210 192.6,210 193.69,211.09 197.6,211.09 ; 197.6,161.09 193.69,161.09 192.6,160 184.75,160 v1(183,158.25) ; 197.6,249.09 193.69,249.09 192.6,248 184.75,248 v1(183,246.25) ; 197.6,123.09 193.69,123.09 192.6,122 184.75,122 v1(183,120.25)
  BOTTOM w0.6: IC14.3 197.6,211.09 ; IC18.3 197.6,123.09 ; IC12.3 197.6,249.09 ; IC16.3 197.6,161.09
  BOTTOM w0.8: 164.56,187.2 R143.2 ; 163.44,187.2 C166.1 163.25,187.08
/PWM2A_BO: length 37.1
  TOP w0.2: v1(154.5,143.5) 156.25,145.25 163,145.25 167.25,149.5 167.25,156.25 164.25,159.25 162.98,159.25
  TOP w0.25: CN4.27 162.98,159.25
  BOTTOM w0.2: 159.22,138.93 159.22,139.53 156.25,142.5 155.5,142.5 v1(154.5,143.5)
  BOTTOM w0.25: 154.5,144.58 v1(154.5,143.5)
  BOTTOM w0.35: 159.22,138.93 IC21.2
  BOTTOM w0.8: R134.2 154.5,144.58
/PWM2B_BO: length 29.5
  TOP w0.2: 157.02,159.25 156,159.25 153.75,157 153.75,143.25 154.25,142.75 155.25,142.75 v1(156,143.5)
  TOP w0.25: CN4.28 157.02,159.25
  BOTTOM w0.2: v1(156,143.5) 159.88,139.62 159.88,138.93
  BOTTOM w0.25: 156,144.58 v1(156,143.5)
  BOTTOM w0.35: 159.88,138.93 IC21.3
  BOTTOM w0.8: R135.2 156,144.58
/PWM3A_BO: length 34.4
  TOP w0.2: v1(157.5,143.5) 158.75,144.75 163.25,144.75 167.75,149.25 167.75,156.5 164.5,159.75 162.98,159.75
  TOP w0.25: CN4.29 162.98,159.75
  BOTTOM w0.2: v1(157.5,143.5) 160.53,140.47 160.53,138.93
  BOTTOM w0.25: 157.5,144.58 v1(157.5,143.5)
  BOTTOM w0.35: 160.53,138.93 IC21.4
  BOTTOM w0.8: R136.2 157.5,144.58
/PWM3B_BO: length 33.7
  TOP w0.2: 157.02,159.75 155.75,159.75 153.25,157.25 153.25,143 154,142.25 157.75,142.25 v1(159,143.5)
  TOP w0.25: 157.02,159.75 CN4.30
  BOTTOM w0.2: 161.18,138.93 161.18,141.32 v1(159,143.5)
  BOTTOM w0.25: 159,144.58 v1(159,143.5)
  BOTTOM w0.35: 161.18,138.93 IC21.5
  BOTTOM w0.8: R137.2 159,144.58
/PWM5A_BO: length 46.3
  TOP w0.2: 162.98,161.25 164.5,161.25 166.5,163.25 166.5,176.5 159.5,183.5 159.5,186.5 158.75,187.25 155,187.25 v1(153.75,186)
  TOP w0.25: CN4.35 162.98,161.25
  BOTTOM w0.2: 159.22,183.93 159.22,184.38 159,184.6 155.15,184.6 v1(153.75,186) 153.75,187.08
  BOTTOM w0.35: IC22.2 159.22,183.93
  BOTTOM w0.8: R138.2 153.75,187.08
/PWM5B_BO: length 36
  TOP w0.2: v1(155.25,186) 153.75,184.5 153.75,163 155.5,161.25 157.02,161.25
  TOP w0.25: 157.02,161.25 CN4.36
  BOTTOM w0.2: 155.25,187.08 v1(155.25,186) 156.25,185 159.25,185 159.88,184.38 159.88,183.93
  BOTTOM w0.35: IC22.3 159.88,183.93
  BOTTOM w0.8: R139.2 155.25,187.08
/PWM6A_BO: length 39.9
  TOP w0.2: 162.98,161.75 164.25,161.75 166,163.5 166,176.25 159,183.25 159,186.25 158.5,186.75 157.5,186.75 v1(156.75,186)
  TOP w0.25: 162.98,161.75 CN4.37
  BOTTOM w0.2: 156.75,187.08 v1(156.75,186) 157.35,185.4 159.85,185.4 160.53,184.72 160.53,183.93
  BOTTOM w0.35: IC22.4 160.53,183.93
  BOTTOM w0.8: R140.2 156.75,187.08
/PWM6B_BO: length 34.7
  TOP w0.2: 157.02,161.75 155.75,161.75 154.25,163.25 154.25,182 v1(158.25,186)
  TOP w0.25: CN4.38 157.02,161.75
  BOTTOM w0.2: 161.18,183.93 161.18,184.82 160,186 v1(158.25,186) 158.25,187.08
  BOTTOM w0.35: IC22.5 161.18,183.93
  BOTTOM w0.8: R141.2 158.25,187.08
/PWM_2A: length 80.9
  TOP w0.3: 137.5,114.61 v1(137.5,116.75)
  TOP w1.7: TP47.1 137.5,114.61
  BOTTOM w0.25: v1(137.5,116.75) 147.5,126.75 163,126.75 163.25,127 164,127 167,130 167,134.75 165.75,136 161.5,136 159.88,134.38 159.88,133.12
  BOTTOM w0.3: v1(137.5,116.75) 136.55,115.8 128.1,115.8 126.8,114.5 ; 126.2,114.5 126.8,113.9 ; 126.2,114.5 125.2,114.5 124.06,113.36 122.4,113.36 ; 126.2,114.5 126.4,114.5 ; 126.8,113.9 126.8,110.6 125.15,108.95 124.44,108.95 ; 126.8,113.9 126.8,114.1 ; 126.8,114.5 126.8,114.1 ; 126.8,114.5 126.4,114.5 ; 126.8,114.1 126.4,114.5
  BOTTOM w0.35: 159.88,133.12 IC21.18
  BOTTOM w0.5: 124.11,108.95 123.61,108.95 123,109.56 122.48,109.56
  BOTTOM w0.6: 122.48,109.56 IC4.8 ; 122.4,113.36 IC4.5
  BOTTOM w0.8: 124.11,108.95 R28.2 124.44,108.95
/PWM_2B: length 95.3
  TOP w0.3: 137.5,152.6 v1(137.5,154.75)
  TOP w1.7: TP48.1 137.5,152.6
  BOTTOM w0.25: v1(137.5,154.75) 138.5,153.75 138.5,135.75 146,128.25 163,128.25 163.25,128 164,128 166.5,130.5 166.5,134.5 165.5,135.5 161.75,135.5 160.53,134.28 160.53,133.12
  BOTTOM w0.3: 126.2,152.5 125.2,152.5 124.06,151.37 122.4,151.37 ; 126.2,152.5 126.8,151.9 ; 126.2,152.5 126.4,152.5 ; 126.8,151.9 126.8,152.1 ; 126.8,151.9 126.8,148.6 125.15,146.95 124.44,146.95 ; 126.8,152.1 126.8,152.5 ; 126.8,152.1 126.4,152.5 ; 126.8,152.5 128.1,153.8 136.55,153.8 v1(137.5,154.75) ; 126.8,152.5 126.4,152.5
  BOTTOM w0.35: IC21.17 160.53,133.12
  BOTTOM w0.5: 124.11,146.95 123.61,146.95 123,147.56 122.48,147.56
  BOTTOM w0.6: 122.48,147.56 IC6.8 ; 122.4,151.37 IC6.5
  BOTTOM w0.8: 124.11,146.95 R40.2 124.44,146.95
/PWM_3A: length 140.5
  TOP w0.3: 137.5,202.6 v1(137.5,204.75)
  TOP w1.7: TP49.1 137.5,202.6
  BOTTOM w0.25: v1(137.5,204.75) 140,202.25 140,136.25 147,129.25 163,129.25 163.25,129.5 164.5,129.5 166,131 166,134.25 165.25,135 162,135 161.18,134.18 161.18,133.12
  BOTTOM w0.3: 126.8,201.9 126.8,198.6 125.15,196.95 124.44,196.95 ; 126.8,201.9 126.8,202.1 ; 126.8,201.9 126.2,202.5 ; 122.4,201.37 124.06,201.37 125.2,202.5 126.2,202.5 ; 126.2,202.5 126.4,202.5 ; 126.8,202.1 126.8,202.5 ; 126.8,202.1 126.4,202.5 ; 126.8,202.5 128.1,203.8 136.55,203.8 v1(137.5,204.75) ; 126.8,202.5 126.4,202.5
  BOTTOM w0.35: IC21.16 161.18,133.12
  BOTTOM w0.5: 122.48,197.56 123,197.56 123.61,196.95 124.11,196.95
  BOTTOM w0.6: 122.48,197.56 IC8.8 ; 122.4,201.37 IC8.5
  BOTTOM w0.8: 124.11,196.95 R52.2 124.44,196.95
/PWM_3B: length 173.7
  TOP w0.3: 137.5,240.6 v1(137.5,242.75)
  TOP w1.7: TP50.1 137.5,240.6
  BOTTOM w0.25: 161.82,133.12 161.82,134.07 162.25,134.5 165,134.5 165.5,134 165.5,131.5 164.5,130.5 163.25,130.5 163,130.75 147.5,130.75 141.5,136.75 141.5,238.75 v1(137.5,242.75)
  BOTTOM w0.3: 126.4,240.5 126.2,240.5 ; 126.4,240.5 126.8,240.1 ; 126.4,240.5 126.8,240.5 ; 126.2,240.5 126.8,239.9 ; 126.2,240.5 125.2,240.5 124.06,239.37 122.4,239.37 ; 126.8,240.1 126.8,240.5 ; 126.8,240.1 126.8,239.9 ; 126.8,240.5 128.1,241.8 136.55,241.8 v1(137.5,242.75) ; 126.8,239.9 126.8,236.6 125.15,234.95 124.44,234.95
  BOTTOM w0.35: IC21.15 161.82,133.12
  BOTTOM w0.5: 124.11,234.95 123.61,234.95 123,235.56 122.48,235.56
  BOTTOM w0.6: 122.4,239.37 IC10.5 ; 122.48,235.56 IC10.8
  BOTTOM w0.8: 124.44,234.95 R64.2 124.11,234.95
/PWM_5A: length 113.7
  TOP w0.3: 182.5,250.4 v1(182.5,248.25)
  TOP w1.7: TP51.1 182.5,250.4
  BOTTOM w0.25: 159.88,178.12 159.88,178.88 161.5,180.5 166,180.5 177.5,192 177.5,243.25 v1(182.5,248.25)
  BOTTOM w0.3: 197.6,251.63 195.94,251.63 194.8,250.5 193.8,250.5 ; 195.56,256.05 194.85,256.05 193.2,254.4 193.2,251.1 ; 193.6,250.5 193.2,250.9 ; 193.6,250.5 193.2,250.5 ; 193.6,250.5 193.8,250.5 ; 193.2,250.9 193.2,251.1 ; 193.2,250.9 193.2,250.5 ; 193.2,251.1 193.8,250.5 ; 193.2,250.5 191.9,249.2 183.45,249.2 v1(182.5,248.25)
  BOTTOM w0.35: IC22.18 159.88,178.12
  BOTTOM w0.5: 197.52,255.44 197,255.44 196.4,256.05 195.9,256.05
  BOTTOM w0.6: 197.52,255.44 IC12.8 ; 197.6,251.63 IC12.5
  BOTTOM w0.8: 195.56,256.05 R75.2 195.9,256.05
/PWM_5B: length 76.2
  TOP w0.3: 182.5,212.4 v1(182.5,210.25)
  TOP w1.7: TP52.1 182.5,212.4
  BOTTOM w0.25: 160.53,178.12 160.53,178.78 161.75,180 167.5,180 179,191.5 179,206.75 v1(182.5,210.25)
  BOTTOM w0.3: 193.6,212.5 193.2,212.9 ; 193.6,212.5 193.2,212.5 ; 193.6,212.5 193.8,212.5 ; 193.2,212.9 193.2,213.1 ; 193.2,212.9 193.2,212.5 ; 193.2,212.5 191.9,211.2 183.45,211.2 v1(182.5,210.25) ; 193.2,213.1 193.2,216.4 194.85,218.05 195.56,218.05 ; 193.2,213.1 193.8,212.5 ; 193.8,212.5 194.8,212.5 195.94,213.63 197.6,213.63
  BOTTOM w0.35: IC22.17 160.53,178.12
  BOTTOM w0.5: 197.52,217.44 197,217.44 196.4,218.05 195.9,218.05
  BOTTOM w0.6: 197.52,217.44 IC14.8 ; 197.6,213.63 IC14.5
  BOTTOM w0.8: 195.56,218.05 R87.2 195.9,218.05
/PWM_6A: length 64.2
  TOP w0.3: 182.5,162.4 v1(182.5,160.25)
  TOP w1.7: TP53.1 182.5,162.4
  BOTTOM w0.25: v1(182.5,160.25) 179,163.75 179,168 167.5,179.5 162,179.5 161.18,178.68 161.18,178.12
  BOTTOM w0.3: v1(182.5,160.25) 183.45,161.2 191.9,161.2 193.2,162.5 ; 195.56,168.05 194.85,168.05 193.2,166.4 193.2,163.1 ; 193.8,162.5 193.2,163.1 ; 193.8,162.5 193.6,162.5 ; 193.8,162.5 194.8,162.5 195.94,163.63 197.6,163.63 ; 193.2,163.1 193.2,162.9 ; 193.2,162.9 193.2,162.5 ; 193.2,162.9 193.6,162.5 ; 193.6,162.5 193.2,162.5
  BOTTOM w0.35: 161.18,178.12 IC22.16
  BOTTOM w0.5: 195.9,168.05 196.4,168.05 197,167.44 197.52,167.44
  BOTTOM w0.6: 197.6,163.63 IC16.5 ; 197.52,167.44 IC16.8
  BOTTOM w0.8: 195.9,168.05 R99.2 195.56,168.05
/PWM_6B: length 100
  TOP w0.3: 182.5,124.39 v1(182.5,122.25)
  TOP w1.7: TP54.1 182.5,124.39
  BOTTOM w0.25: v1(182.5,122.25) 177.5,127.25 177.5,167.5 166,179 162.25,179 161.82,178.57 161.82,178.12
  BOTTOM w0.3: 193.6,124.5 193.2,124.9 ; 193.6,124.5 193.8,124.5 ; 193.6,124.5 193.2,124.5 ; 193.2,124.9 193.2,124.5 ; 193.2,124.9 193.2,125.1 ; 193.8,124.5 193.2,125.1 ; 193.8,124.5 194.8,124.5 195.94,125.64 197.6,125.64 ; 193.2,125.1 193.2,128.4 194.85,130.05 195.56,130.05 ; v1(182.5,122.25) 183.45,123.2 191.9,123.2 193.2,124.5
  BOTTOM w0.35: IC22.15 161.82,178.12
  BOTTOM w0.5: 195.9,130.05 196.4,130.05 197,129.44 197.52,129.44
  BOTTOM w0.6: 197.6,125.64 IC18.5 ; 197.52,129.44 IC18.8
  BOTTOM w0.8: 195.56,130.05 R111.2 195.9,130.05
AD0: length 113.9
  TOP w0.2: 150.66,63.08 150.66,63.59 146.5,67.75 146.5,72 145.5,73 v1(143.25,73) ; v1(165,154) 164.25,154.75 162.98,154.75
  TOP w0.25: CN4.9 162.98,154.75
  TOP w0.6: IC19.1 150.66,63.08
  BOTTOM w0.2: 142.95,70.4 142.95,71.6 ; v1(165,154) 165,150.25 168.5,146.75 168.5,125.25 152,108.75 152,81.75 v1(143.25,73) 142.95,72.7 C15.1
  BOTTOM w0.8: R18.1 142.95,70.4 ; 142.95,71.6 C15.1
AD1: length 133.7
  TOP w0.2: 157.02,154.75 155.75,154.75 155.25,154.25 155.25,152.25 156.25,151.25 v1(166.5,151.25) ; 149.38,55.75 148.5,55.75 148.12,56.13 148.12,56.89 ; 149.38,55.75 v1(154,55.75) ; 149.38,55.75 149.38,56.92
  TOP w0.25: CN4.10 157.02,154.75
  TOP w0.6: IC19.6 148.12,56.89 ; 149.38,56.92 IC19.7
  BOTTOM w0.2: v1(154,55.75) 158.75,60.5 158.75,78.25 153,84 153,108.25 169.5,124.75 169.5,148.25 v1(166.5,151.25)
AD2: length 99.1
  TOP w0.2: 162.98,155.75 164.75,155.75 v1(165,156) ; C168.2 152.95,81.45 v1(153.25,81.75) 155,81.75 158,78.75 158,76 157.79,75.79 157.14,75.79 ; 152.95,79.15 152.95,80.35
  TOP w0.25: CN4.13 162.98,155.75
  TOP w0.5: IC1.14 157.14,75.79
  TOP w0.8: 152.95,80.35 C168.2 ; R155.1 152.95,79.15
  BOTTOM w0.2: v1(165,156) 165.75,155.25 165.75,150.75 169,147.5 169,125 152.5,108.5 152.5,82.5 v1(153.25,81.75)
AD3: length 146.2
  TOP w0.2: 157.02,155.75 155.25,155.75 v1(155,156) ; 172.09,71.71 172.54,71.71 v1(173,71.25)
  TOP w0.25: CN4.14 157.02,155.75
  TOP w0.5: IC24.8 172.09,71.71
  BOTTOM w0.2: C154.1 177.05,37.8 176.75,37.5 174.75,37.5 173.75,38.5 173.75,70.5 v1(173,71.25) 173.75,72 173.75,74.25 170.5,77.5 170.5,154 166.25,158.25 161,158.25 158.75,156 v1(155,156) ; 177.05,39.85 177.05,38.65
  BOTTOM w0.8: 177.05,38.65 C154.1 ; R120.1 177.05,39.85
AD4: length 95.8
  TOP w0.2: 167.95,79.15 167.95,80.35 ; v1(164,157) 163.75,156.75 162.98,156.75 ; C171.2 167.95,81.45 v1(168.25,81.75) 170,81.75 173,78.75 173,76 172.79,75.79 172.14,75.79
  TOP w0.25: CN4.17 162.98,156.75
  TOP w0.5: IC24.14 172.14,75.79
  TOP w0.8: 167.95,80.35 C171.2 ; R158.1 167.95,79.15
  BOTTOM w0.2: v1(164,157) 164.75,157.75 166,157.75 170,153.75 170,83.5 v1(168.25,81.75)
HV_DC_CURRENT: length 45.7
  TOP w0.2: 139.12,39.95 144.55,39.95 145.75,38.75 147.28,38.75 ; v1(149,72.75) 149.35,73.1 150.32,73.1 ; TP1.1 v1(147.5,40.5)
  TOP w0.35: IC1.5 150.32,73.1
  TOP w1.5: 139.12,39.95 CT1.12
  TOP w1.7: TP1.1 147.28,38.75
  BOTTOM w0.2: v1(149,72.75) 148.75,72.5 148.75,41.75 v1(147.5,40.5)
HV_DC_CURRENT_REF: length 43
  TOP w0.2: 150.32,74.4 149.35,74.4 v1(149,74.75) ; 139.12,41.86 143.86,41.86 145.75,43.75 147.28,43.75 ; TP57.1 v1(147.5,45.5)
  TOP w0.35: IC1.3 150.32,74.4
  TOP w1.5: 139.12,41.86 CT1.11
  TOP w1.7: TP57.1 147.28,43.75
  BOTTOM w0.2: v1(147.5,45.5) 148.25,46.25 148.25,74 v1(149,74.75)
HV_DC_N: length 108.2
  CONDUCTIVE3 w1: C6.2 60.5,88.04 ; C6.2 65.5,88.04 ; C6.2 62.96,90.5 ; C6.2 62.96,85.5 ; C7.2 91.5,88.04 ; C7.2 93.96,90.5 ; C7.2 93.96,85.5 ; C7.2 96.5,88.04 ; R7.2 72.5,29.5 ; R7.2 67.75,29.5 ; R7.2 70.25,31.75 ; R7.2 70.25,27.5 ; C5.2 31.96,85.5 ; C5.2 34.5,88.04 ; C5.2 31.96,90.5 ; C5.2 29.5,88.04
  BOTTOM w0.2: 127,68.87 D6.A 127,67.95
  BOTTOM w0.5: 127,70.09 127,69.02
  BOTTOM w0.8: 113.75,70.5 122.75,70.5 123.75,69.5 R15.2 C14.2 125.72,69.02 127,69.02 ; 127,69.02 127,68.87 ; 127,69.02 130.19,69.02 ; R17.1 127,70.09
  BOTTOM w1: C7.2 97.25,88.04 ; C7.2 90.75,88.04 ; C7.2 93.96,91.25 ; C7.2 93.96,84.75 ; R7.2 70.25,27.25 ; R7.2 72.5,29.5 ; R7.2 70.25,31.75 ; R7.2 68.25,29.5 ; C6.2 66.5,88.04 ; C6.2 59.75,88.04 ; C6.2 62.96,91.25 ; C6.2 62.96,84.75 ; C5.2 31.96,91.5 ; C5.2 31.96,84.75 ; C5.2 35.25,88.04 ; C5.2 28.5,88.04
  BOTTOM w1.5: IC2.3 130.19,69.02
  vias: v2(46.25,247.25) v2(46.25,245.25) v2(46.25,243.25) v2(46.25,241.25) v2(46.25,198.75) v2(46.25,196.75) v2(46.25,194.75) v2(46.25,192.75) v2(46.25,159.25) v2(46.25,157.25) v2(46.25,155.25) v2(46.25,153.25) v2(46.25,110.75) v2(46.25,108.75) v2(46.25,106.75) v2(46.25,104.75)
HV_DC_P: length 68.2
  CONDUCTIVE5 w1: C2.1 35.75,47.96 ; C2.1 39.04,51.25 ; C2.1 39.04,44.75 ; C2.1 42.5,47.96 ; C4.1 101.04,44.75 ; C4.1 97.75,47.96 ; C4.1 104.5,47.96 ; C4.1 101.04,51.25 ; C3.1 66.75,47.96 ; C3.1 73.5,47.96 ; C3.1 70.04,51.25 ; C3.1 70.04,44.75 ; R1.1 60.5,29.5 ; R1.1 62.75,31.75 ; R1.1 64.75,29.5 ; R1.1 62.75,27.5
  BOTTOM w0.8: R10.1 101.04,58.94 C4.1
  vias: v2(75.75,198.75) v2(75.75,196.75) v2(75.75,194.75) v2(75.75,192.75) v2(75.75,190.75) v2(75.75,188.75) v2(75.75,186.75) v2(75.75,184.75) v2(75.75,182.75) v2(75.75,180.75) v2(75.75,110.75) v2(75.75,108.75) v2(75.75,106.75) v2(75.75,104.75)
LV_DC_CURRENT: length 62.5
  TOP w0.2: TP42.1 v1(172.5,26.75) ; 165.32,73.1 164.35,73.1 v1(164,72.75) ; 180.88,24.05 175.2,24.05 174.25,25 172.72,25
  TOP w0.35: IC24.5 165.32,73.1
  TOP w1.5: 180.88,24.05 CT2.12
  TOP w1.7: TP42.1 172.72,25
  BOTTOM w0.2: v1(164,72.75) 163.75,72.5 163.75,35.5 v1(172.5,26.75)
LV_DC_CURRENT_REF: length 70.4
  TOP w0.2: 172.72,20 174.25,20 176.39,22.14 180.88,22.14 ; 165.32,74.4 164.35,74.4 v1(164,74.75) ; TP58.1 v1(172.5,21.75)
  TOP w0.35: IC24.3 165.32,74.4
  TOP w1.5: 180.88,22.14 CT2.11
  TOP w1.7: TP58.1 172.72,20
  BOTTOM w0.2: v1(164,74.75) 163.25,74 163.25,34.75 172.5,25.5 v1(172.5,21.75)
LV_DC_N: length 152.9
  CONDUCTIVE3 w1: C152.2 226.04,30.5 ; C152.2 226.04,25.5 ; C152.2 223.5,27.96 ; C152.2 228.5,27.96 ; C150.2 290.5,27.96 ; C150.2 288.04,30.5 ; C150.2 285.5,27.96 ; C150.2 288.04,25.5 ; C149.2 223.5,60.96 ; C149.2 226.04,63.5 ; C149.2 226.04,58.5 ; C149.2 228.5,60.96 ; C148.2 257.04,58.25 ; C148.2 259.5,60.96 ; C148.2 257.04,63.5 ; C148.2 254.5,60.96 ; C147.2 288.04,58.5 ; C147.2 288.04,63.5 ; C147.2 285.5,60.96 ; C147.2 290.5,60.96 ; C151.2 259.5,27.96 ; C151.2 257.04,30.5 ; C151.2 257.04,25.5 ; C151.2 254.5,27.96
  BOTTOM w0.2: 193,42.3 D58.A 193,41.23
  BOTTOM w0.5: 193,40.16 193,41.12
  BOTTOM w0.8: 189.81,41.23 193,41.23 ; 193,41.23 194.28,41.23 C157.2 R131.2 196.25,40.75 197,40 198.75,40 ; 193,41.23 193,41.12 ; R130.1 193,40.16
  BOTTOM w1: C151.2 257.04,31.25 ; C151.2 253.75,27.96 ; C151.2 260.5,27.96 ; C151.2 257.04,24.5 ; C147.2 288.04,57.75 ; C147.2 291.25,60.96 ; C147.2 284.75,60.96 ; C147.2 288.04,64.25 ; C150.2 288.04,24.75 ; C150.2 288.04,31.25 ; C150.2 291.5,27.96 ; C150.2 284.75,27.96 ; C149.2 226.04,64.25 ; C149.2 229,60.96 ; C149.2 222.5,60.96 ; C149.2 226.04,57.75 ; C148.2 257.04,57.75 ; C148.2 254,60.96 ; C148.2 260.5,60.96 ; C148.2 257.04,64.25 ; C152.2 229.5,27.96 ; C152.2 226.04,24.5 ; C152.2 226.04,31.25 ; C152.2 222.5,27.96
  BOTTOM w1.5: IC20.3 189.81,41.23
  vias: v2(273.75,260.25) v2(273.75,258.25) v2(273.75,256.25) v2(273.75,254.25) v2(273.75,211.75) v2(273.75,209.75) v2(273.75,207.75) v2(273.75,205.75) v2(273.75,172.25) v2(273.75,170.25) v2(273.75,168.25) v2(273.75,166.25) v2(273.75,123.75) v2(273.75,121.75) v2(273.75,119.75) v2(273.75,117.75)
LV_DC_P: length 151.6
  CONDUCTIVE2 w1: C148.1 252.5,68.04 ; C148.1 249.96,70.75 ; C148.1 249.96,65.5 ; C148.1 247.5,68.04 ; C150.1 280.96,37.5 ; C150.1 283.5,35.04 ; C150.1 278.5,35.04 ; C150.1 280.96,32.5 ; C147.1 280.96,70.5 ; C147.1 280.96,65.5 ; C147.1 283.75,68.04 ; C147.1 278.5,68.04 ; C152.1 221.5,35.04 ; C152.1 216.5,35.04 ; C152.1 218.96,32.5 ; C152.1 218.96,37.5 ; C149.1 218.96,65.5 ; C149.1 221.5,68.04 ; C149.1 218.96,70.75 ; C149.1 216.5,68.04 ; C151.1 247.5,35.04 ; C151.1 249.96,32.5 ; C151.1 249.96,37.75 ; C151.1 252.5,35.04
  CONDUCTIVE5 w1: C148.1 253.25,68.04 ; C148.1 249.96,71.25 ; C148.1 246.75,68.04 ; C148.1 249.96,65 ; C151.1 253.25,35.04 ; C151.1 249.96,31.75 ; C151.1 246.75,35.04 ; C151.1 249.96,38.5 ; C149.1 215.75,68.04 ; C149.1 222.25,68.04 ; C149.1 218.96,71.25 ; C149.1 218.96,65 ; C152.1 218.96,38.5 ; C152.1 222.25,35.04 ; C152.1 215.75,35.04 ; C152.1 218.96,31.75 ; C147.1 284.5,68.04 ; C147.1 277.75,68.04 ; C147.1 280.96,71.5 ; C147.1 280.96,64.75 ; C150.1 280.96,38.25 ; C150.1 284.25,35.04 ; C150.1 280.96,32 ; C150.1 278,35.04
  BOTTOM w0.8: C152.1 218.96,38.59 R128.1
  vias: v2(244.25,260.25) v2(244.25,258.25) v2(244.25,256.25) v2(244.25,254.25) v2(244.25,184.25) v2(244.25,182.25) v2(244.25,180.25) v2(244.25,178.25) v2(244.25,176.25) v2(244.25,174.25) v2(244.25,172.25) v2(244.25,170.25) v2(244.25,168.25) v2(244.25,166.25)
N15594553: length 21.4
  BOTTOM w0.45: 111.66,110.83 110.83,110.83 110.5,110.5 110.5,108.5 109.65,107.65 104.15,107.65 103.25,106.75 97.75,106.75 96.75,107.75 94.25,107.75
  BOTTOM w0.6: IC4.10 111.66,110.83
N15594591: length 18.9
  TOP w0.5: v2(100.4,118) 100.4,118.9 101.8,120.3 104.45,120.3 106,118.75 108.75,118.75 110.5,117 v2(110.5,116) 113.15,116
  TOP w1.7: 113.15,116 TP3.1
  BOTTOM w0.6: v2(110.5,116) 111.09,115.91 IC4.14
N15594597: length 13.4
  BOTTOM w0.45: 111.55,112.09 110.59,112.09 109.5,111 109.5,109 109.1,108.6 101.75,108.6 101.75,108.5
  BOTTOM w0.6: IC4.11 111.55,112.09
N15594617: length 6.5
  TOP w1: v2(93.5,117) 93.3,117.2 91.85,117.2
  TOP w1.4: D8.A 91.85,117.2
  BOTTOM w0.8: R24.2 v2(93.5,117)
N15594699: length 6.9
  BOTTOM w0.5: 124.23,110.55 123.45,110.55 123.17,110.83 122.48,110.83 ; 122.48,112.09 123.53,112.09 124,112 ; 124.25,110.8 124.25,111.28 124.2,111.75
  BOTTOM w0.6: 122.48,112.09 IC4.6 ; 122.48,110.83 IC4.7
  BOTTOM w0.8: 124.23,110.55 R28.1 124.25,110.8 ; 124.2,111.75 R23.2 124,112
N15594761: length 5.5
  TOP w0.5: 98.64,109.67 98.64,108.52 R22.1 ; C19.2 101.22,108.05 100.47,108.05 ; 99.02,108.05 99.98,108.05
  TOP w0.6: 98.64,109.67 IC3.7
  TOP w0.8: 100.47,108.05 R20.2 99.98,108.05 ; R22.1 99.02,108.05
N15594765: length 1.5
  TOP w0.5: 101.42,106.5 100.95,106.45 100.27,106.45
  TOP w0.8: R20.1 100.27,106.45 ; 101.42,106.5 R21.2
N15594863: length 5.5
  TOP w0.5: 99.02,146.05 99.98,146.05 ; C39.2 101.22,146.05 100.47,146.05 ; 98.64,147.67 98.64,146.52 R33.1
  TOP w0.6: 98.64,147.67 IC5.7
  TOP w0.8: 100.47,146.05 R34.2 99.98,146.05 ; R33.1 99.02,146.05
N15594957: length 18.9
  TOP w0.5: 113.15,154 v2(110.5,154) 110.5,155 108.75,156.75 106,156.75 104.45,158.3 101.8,158.3 100.4,156.9 v2(100.4,156)
  TOP w1.7: 113.15,154 TP8.1
  BOTTOM w0.6: v2(110.5,154) 111.09,153.91 IC6.14
N15594961: length 6.5
  TOP w1: v2(93.5,155) 93.3,155.2 91.85,155.2
  TOP w1.4: D14.A 91.85,155.2
  BOTTOM w0.8: R36.2 v2(93.5,155)
N15594967: length 6.9
  BOTTOM w0.5: 124.2,149.75 124.25,149.28 124.25,148.79 ; 124.23,148.55 123.45,148.55 123.17,148.82 122.48,148.82 ; 124,150 123.53,150.09 122.48,150.09
  BOTTOM w0.6: 122.48,148.82 IC6.7 ; 122.48,150.09 IC6.6
  BOTTOM w0.8: 124.2,149.75 R35.2 124,150 ; 124.25,148.79 R40.1 124.23,148.55
N15595025: length 13.4
  BOTTOM w0.45: 111.55,150.09 110.59,150.09 109.5,149 109.5,147 109.1,146.6 101.75,146.6 101.75,146.5
  BOTTOM w0.6: IC6.11 111.55,150.09
N15595027: length 21.4
  BOTTOM w0.45: 94.25,145.75 96.75,145.75 97.75,144.75 103.25,144.75 104.15,145.65 109.65,145.65 110.5,146.5 110.5,148.5 110.83,148.82 111.66,148.82
  BOTTOM w0.6: IC6.10 111.66,148.82
N15597681: length 21.4
  BOTTOM w0.45: 111.66,198.82 110.83,198.82 110.5,198.5 110.5,196.5 109.65,195.65 104.15,195.65 103.25,194.75 97.75,194.75 96.75,195.75 94.25,195.75
  BOTTOM w0.6: IC8.10 111.66,198.82
N15597719: length 18.9
  TOP w0.5: 113.15,204 v2(110.5,204) 110.5,205 108.75,206.75 106,206.75 104.45,208.3 101.8,208.3 100.4,206.9 v2(100.4,206)
  TOP w1.7: 113.15,204 TP13.1
  BOTTOM w0.6: IC8.14 111.09,203.91 v2(110.5,204)
N15597725: length 13.4
  BOTTOM w0.45: 101.75,196.5 101.75,196.6 109.1,196.6 109.5,197 109.5,199 110.59,200.09 111.55,200.09
  BOTTOM w0.6: IC8.11 111.55,200.09
N15597745: length 6.5
  TOP w1: v2(93.5,205) 93.3,205.2 91.85,205.2
  TOP w1.4: D20.A 91.85,205.2
  BOTTOM w0.8: R48.2 v2(93.5,205)
N15597827: length 6.9
  BOTTOM w0.5: 124.2,199.75 124.25,199.28 124.25,198.79 ; 122.48,200.09 123.53,200.09 124,200 ; 124.23,198.55 123.45,198.55 123.17,198.82 122.48,198.82
  BOTTOM w0.6: 122.48,198.82 IC8.7 ; 122.48,200.09 IC8.6
  BOTTOM w0.8: 124.23,198.55 R52.1 124.25,198.79 ; 124.2,199.75 R47.2 124,200
N15597889: length 5.5
  TOP w0.5: 98.64,197.67 98.64,196.52 R46.1 ; 99.02,196.05 99.98,196.05 ; 100.47,196.05 101.22,196.05 C51.2
  TOP w0.6: 98.64,197.67 IC7.7
  TOP w0.8: 99.98,196.05 R44.2 100.47,196.05 ; R46.1 99.02,196.05
N15597991: length 5.5
  TOP w0.5: R58.1 98.64,234.52 98.64,235.67 ; 100.47,234.05 101.22,234.05 C71.2 ; 99.02,234.05 99.98,234.05
  TOP w0.6: 98.64,235.67 IC9.7
  TOP w0.8: R58.1 99.02,234.05 ; 99.98,234.05 R56.2 100.47,234.05
N15598085: length 18.9
  TOP w0.5: v2(100.4,244) 100.4,244.9 101.8,246.3 104.45,246.3 106,244.75 108.75,244.75 110.5,243 v2(110.5,242) 113.15,242
  TOP w1.7: 113.15,242 TP18.1
  BOTTOM w0.6: v2(110.5,242) 111.09,241.91 IC10.14
N15598089: length 6.5
  TOP w1: 91.85,243.2 93.3,243.2 v2(93.5,243)
  TOP w1.4: D26.A 91.85,243.2
  BOTTOM w0.8: R60.2 v2(93.5,243)
